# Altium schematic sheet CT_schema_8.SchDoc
size 274 x 160 mm
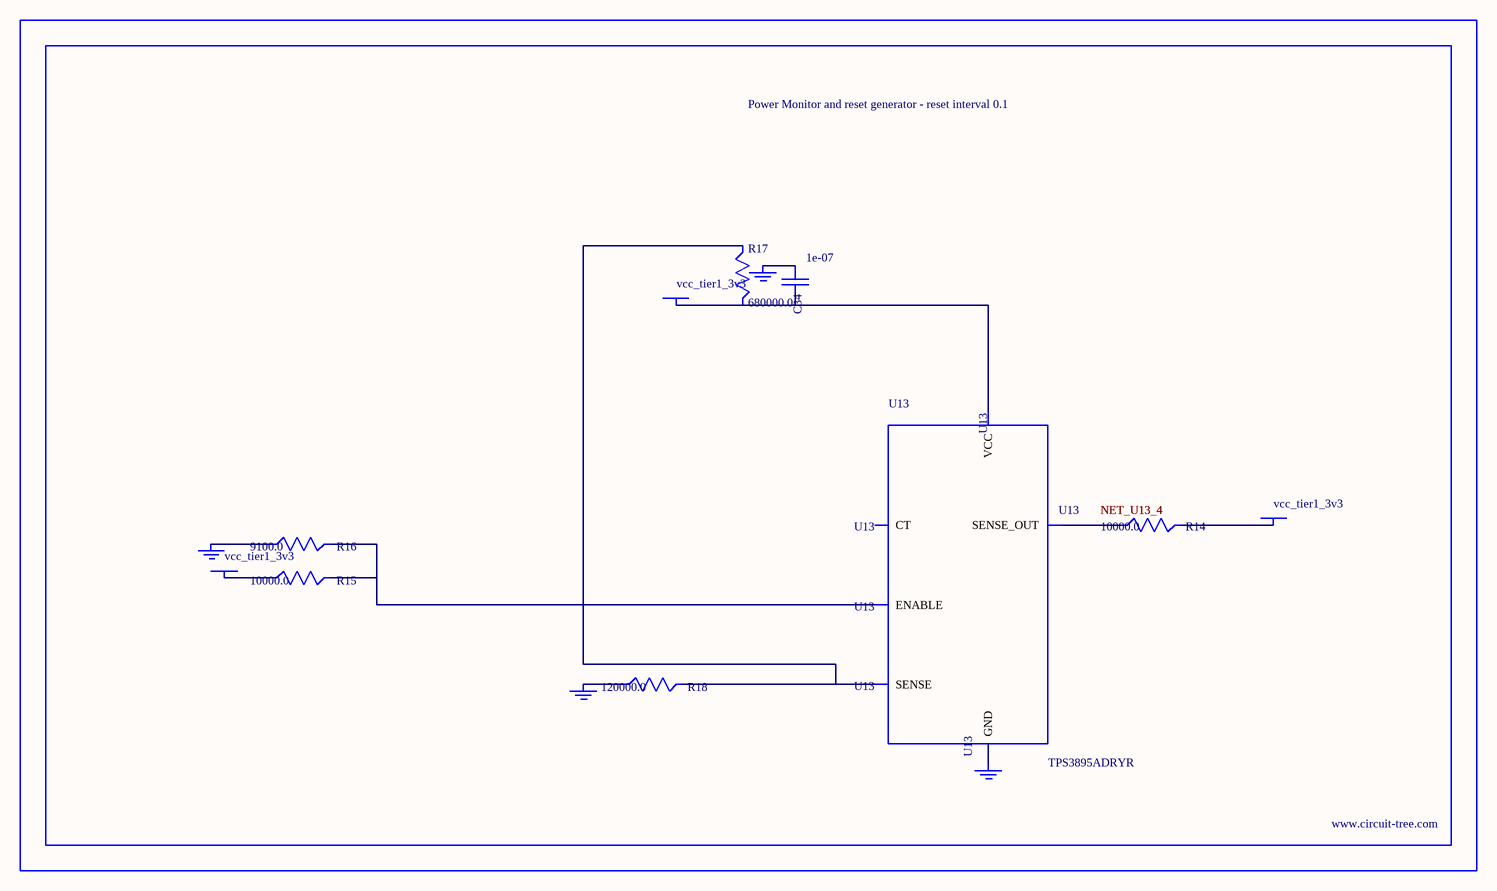
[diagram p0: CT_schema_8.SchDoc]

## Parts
BORDER7  (no value)
C34  1e-07  [C0402]
GND_INSTANCE_7_0  (no value)
GND_INSTANCE_7_1  (no value)
GND_INSTANCE_7_2  (no value)
GND_INSTANCE_7_3  (no value)
POWER_INSTANCE_7_0  vcc_tier1_3v3
POWER_INSTANCE_7_1  vcc_tier1_3v3
POWER_INSTANCE_7_2  vcc_tier1_3v3
R14  10000.0  [R0603]
R15  10000.0  [R0603]
R16  9100.0  [R0603]
R17  680000.0  [R0603]
R18  120000.0  [R0603]
U13  TPS3895ADRYR  [SON-6]

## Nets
NetC34_1: C34.1 GND_INSTANCE_7_2.0(GND)
NetC34_2: C34.2 POWER_INSTANCE_7_2.0(PWR) R17.2 U13.6(VCC)
NetGND_INSTANCE_7_0_0: GND_INSTANCE_7_0.0(GND) R16.1
NetGND_INSTANCE_7_1_0: GND_INSTANCE_7_1.0(GND) R18.1
NetGND_INSTANCE_7_3_0: GND_INSTANCE_7_3.0(GND) U13.2(GND)
NetPOWER_INSTANCE_7_0_0: POWER_INSTANCE_7_0.0(PWR) R15.1
NetPOWER_INSTANCE_7_1_0: POWER_INSTANCE_7_1.0(PWR) R14.2
NetR14_1: R14.1 U13.4(SENSE_OUT)
NetR15_2: R15.2 R16.2 U13.1(ENABLE)
NetR17_1: R17.1 R18.2 U13.3(SENSE)

Not connected (* = marked no-connect by the designer): U13 5(CT)

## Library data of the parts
BORDER7 = BORDER_PAGE7
C34 = C0402C104K3RACTU
GND_INSTANCE_7_0-GND_INSTANCE_7_3 = GND
POWER_INSTANCE_7_0-POWER_INSTANCE_7_2 = PWR
R14 R15 = RC0603JR-0710KL
R16 = RC0603JR-079K1L
R17 = RC0603JR-07680KL
R18 = RC0603JR-07120KL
